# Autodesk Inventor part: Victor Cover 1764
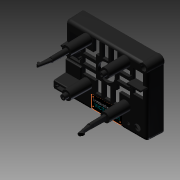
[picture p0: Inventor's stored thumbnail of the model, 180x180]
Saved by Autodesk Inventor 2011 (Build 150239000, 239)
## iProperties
Shininess: 64.0
Length Units: 11272
Angle Units: 11279
Time Units: 11290
Mass Units: 11286
Length Display Precision: 3
Angle Display Precision: 2
Compacted: True
Part Number: Victor Cover 1764
Document SubType Name: Modeling
Created: 2007-01
Designer: uidk0133
Density: 1 g/cm^3
Density: 0.0
Volumn: 0.0
Area: 0.0
PropertySet Name: Model Information
Control State: 0
Master: False
Checked Out: False
Translation Standard: STEP AP203
File Name: V883-002 RevH.stp
Preprocessor: THINKDESIGN
Postprocessor: Build: Release: 6 RTM Build: 90b - Date: Tue 09/24/2002
Sent Units: INCHES
Uncertainty: 0.0
Author: uidk0133
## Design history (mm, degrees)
feature "Base1"
sketch "Label"
  geometry: L1 (22.225, 0)-(0, 0) reference; L2 (-1.905, -1.905)-(-1.905, -8.89) reference; L3 (0, -10.795)-(22.225, -10.795) reference; L4 (24.13, -8.89)-(24.13, -1.905) reference; L5 (-1.905, 0)-(24.13, 0); L6 (24.13, 0)-(24.13, -11.121); L7 (24.13, -11.121)-(-1.905, -11.121); L8 (-1.905, -11.121)-(-1.905, 0); L9 (-1.905, -1.905)-(-1.905, -8.89) reference; L10 (24.13, -8.89)-(24.13, -1.905) reference; L11 (22.225, 0)-(0, 0) reference; A1 r 1.905 centre (22.225, -1.905) between (24.13, -1.905) and (22.225, 0) reference; A2 r 1.905 centre (0, -1.905) between (0, 0) and (-1.905, -1.905) reference; A3 r 1.905 centre (0, -8.89) between (-1.905, -8.89) and (0, -10.795) reference; A4 r 1.905 centre (22.225, -8.89) between (22.225, -10.795) and (24.13, -8.89) reference; 1 other entity
  constraints: 3 collinear, 2 other
  node "Image2"
body "Solid1"
